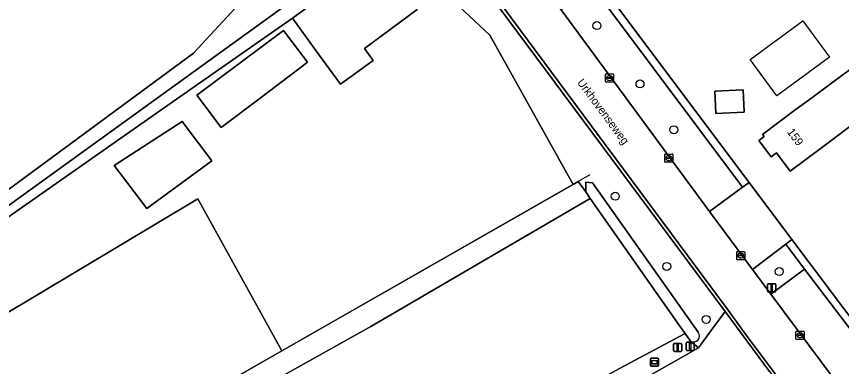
# Model space of a CAD drawing. Extents: x 164494 to 166241, y 382475 to 384495.
# Drawn here: x 164917.8 to 165019, y 383217.5 to 383260.4 of the extents above; entities that cross this region are included whole.
import ezdxf

# ---------------------------------------------------------------- set-up
doc = ezdxf.new("R2010")
doc.units = 0
for name, color, linetype in [('IMGEO_Afsluitpaal', 7, 'Continuous'), ('IMGEO_Berm_halfverhard', 7, 'Continuous'), ('IMGEO_Boom', 7, 'Continuous'), ('IMGEO_Erf', 7, 'Continuous'), ('IMGEO_Grasland_agrarisch', 7, 'Continuous'), ('IMGEO_Grasland_overig', 7, 'Continuous'), ('IMGEO_Groenvoorziening', 7, 'Continuous'), ('IMGEO_Hek', 7, 'Continuous'), ('IMGEO_Informatiebord', 7, 'Continuous'), ('IMGEO_Kolk', 7, 'Continuous'), ('IMGEO_Lichtmast', 7, 'Continuous'), ('IMGEO_Openbare_ruimte_label', 7, 'Continuous'), ('IMGEO_Pand', 7, 'Continuous'), ('IMGEO_Pand_nummerreeks', 7, 'Continuous'), ('IMGEO_Pand_vergunning_verleend', 7, 'Continuous'), ('IMGEO_Parkeervlak_open', 7, 'Continuous'), ('IMGEO_Rijbaan_lokaal_gesloten', 7, 'Continuous'), ('IMGEO_Voetpad_halfverhard', 7, 'Continuous'), ('IMGEO_Voetpad_open', 7, 'Continuous'), ('IMGEO_Waterloop', 7, 'Continuous')]:
    doc.layers.add(name, color=color, linetype=linetype)

msp = doc.modelspace()

# ---------------------------------------------------------------- linework, layer by layer
at = {"layer": 'IMGEO_Afsluitpaal'}
for p, q in [((165000.02, 383220.51), (165000.81, 383220.51)), ((165000.81, 383220.51), (165000.02, 383220.51)), ((164998.39, 383219.47), (164998.39, 383220.27)), ((164998.39, 383220.27), (164998.39, 383219.47)), ((164998.49, 383220.37), (164999.28, 383220.37)), ((164999.28, 383220.37), (164998.49, 383220.37)), ((164999.38, 383220.27), (164999.38, 383219.47)), ((164999.38, 383219.47), (164999.38, 383220.27)), ((164999.92, 383219.61), (164999.92, 383220.41)), ((164999.92, 383220.41), (164999.92, 383219.61)), ((165000.81, 383219.51), (165000.02, 383219.51)), ((165000.02, 383219.51), (165000.81, 383219.51)), ((165000.91, 383220.41), (165000.91, 383219.61)), ((165000.91, 383219.61), (165000.91, 383220.41)), ((164999.28, 383219.37), (164998.49, 383219.37)), ((164998.49, 383219.37), (164999.28, 383219.37))]:
    msp.add_line(p, q, dxfattribs=at)
for points in [[(164998.81, 383220.24), (164998.96, 383220.24), (164998.96, 383219.49), (164998.81, 383219.49), (164998.81, 383220.24)], [(165000.34, 383220.39), (165000.49, 383220.39), (165000.49, 383219.64), (165000.34, 383219.64), (165000.34, 383220.39)]]:
    msp.add_lwpolyline(points, dxfattribs=at)
for centre, start, end in [((165000.02, 383220.41), 90, 180), ((165000.02, 383220.41), 90, 180), ((165000.81, 383220.41), 0, 90), ((165000.81, 383220.41), 360, 90), ((164998.49, 383220.27), 90, 180), ((164998.49, 383220.27), 90, 180), ((164998.49, 383219.47), 180, 270), ((164998.49, 383219.47), 180, 270), ((164999.28, 383220.27), 0, 90), ((164999.28, 383220.27), 360, 90), ((164999.28, 383219.47), 270, 0), ((164999.28, 383219.47), 270, 0), ((165000.02, 383219.61), 180, 270), ((165000.02, 383219.61), 180, 270), ((165000.81, 383219.61), 270, 0), ((165000.81, 383219.61), 270, 0)]:
    msp.add_arc(centre, 0.1, start, end, dxfattribs=at)
at = {"layer": 'IMGEO_Berm_halfverhard'}
msp.add_lwpolyline([(164958.62, 383286.84), (164958.17, 383286.49), (164958.55, 383285.99), (164958.68, 383286.07), (164960.2, 383284.12), (164981.5, 383255.45), (165004.7, 383224.27), (165010.16, 383216.93), (165012.66, 383213.57), (165041.52, 383174.67), (165059.93, 383149.88), (165074.19, 383130.82), (165074.54, 383131.07), (165010.83, 383216.64), (165007.31, 383221.33), (165004.94, 383224.6), (164967.78, 383274.69)], close=True, dxfattribs=at)
at = {"layer": 'IMGEO_Boom'}
for centre in [(164988.99, 383259.29), (164994.27, 383252.14), (164998.41, 383246.53), (164991.24, 383238.38), (164997.55, 383229.79), (165011.34, 383229.17), (165002.38, 383223.31)]:
    msp.add_circle(centre, 0.489, dxfattribs=at)
at = {"layer": 'IMGEO_Erf'}
msp.add_lwpolyline([(165023.92, 383258.65), (165006.08, 383283.99), (165005.99, 383284.12), (164985.66, 383269.16), (164989.23, 383264.62), (164989.47, 383264.32), (165007.64, 383240.09), (165012.9, 383233.07), (165015.24, 383229.95), (165031.24, 383208.7)], dxfattribs=at)
for points in [[(164975.85, 383258.13), (164970.17, 383263.46), (164965.56, 383269.95), (164955.81, 383263.21), (164956.74, 383261.95), (164963.02, 383266.55), (164966.97, 383261.24), (164960.49, 383256.48), (164961.55, 383255.02), (164957.55, 383252.11), (164954.88, 383255.78), (164951.66, 383260.2), (164937.06, 383250), (164897.83, 383222.54), (164900.71, 383215.89), (164901.16, 383214.86), (164940.07, 383238.06), (164950.37, 383219.45), (164986.06, 383239.83)], [(164942.93, 383246.82), (164939.97, 383250.76), (164950.58, 383258.7), (164953.52, 383254.79), (164952.62, 383254.12), (164947.54, 383250.29)], [(165016.69, 383244.44), (165012.69, 383241.44), (165010.98, 383243.72), (165010.33, 383243.23), (165008.84, 383245.21), (165009.49, 383245.7), (165009.3, 383245.95), (165013.3, 383248.95), (165014.72, 383250), (165019.93, 383253.86), (165021.79, 383251.27), (165023.19, 383249.33), (165021.63, 383248.16)], [(165003.56, 383248.53), (165003.45, 383251.26), (165006.92, 383251.41), (165007.04, 383248.68)], [(164941.79, 383242.72), (164933.81, 383236.88), (164929.82, 383242.15), (164938.15, 383247.53)]]:
    msp.add_lwpolyline(points, close=True, dxfattribs=at)
at = {"layer": 'IMGEO_Grasland_agrarisch'}
for points in [[(164934.11, 383311.92), (164929.02, 383318.47), (164901.77, 383355.27), (164897.46, 383360.39), (164834.21, 383297.03), (164834.1, 383296.91), (164881.99, 383247.23), (164898.48, 383225.71), (164939.55, 383255.93), (164960.04, 383278.08), (164955.63, 383284.19), (164935.17, 383310.55), (164875.47, 383265.01), (164875, 383265.61)], [(164903.86, 383190.4), (164907.46, 383171.6), (164949.35, 383194.41), (164992.36, 383217.63), (164999.81, 383221.56), (164999.17, 383222.48), (164988.18, 383238.12), (164961.27, 383222.45)]]:
    msp.add_lwpolyline(points, close=True, dxfattribs=at)
at = {"layer": 'IMGEO_Grasland_overig'}
for points in [[(164959.97, 383268.39), (164897.51, 383223.29), (164897.83, 383222.54), (164937.06, 383250), (164951.66, 383260.2), (164955.81, 383263.21), (164965.56, 383269.95), (164963.61, 383272.68)], [(164961.27, 383222.45), (164988.18, 383238.12), (164987.61, 383238.93), (164986.71, 383240.2), (164986.06, 383239.83), (164950.37, 383219.45), (164903.43, 383192.65), (164903.86, 383190.4)], [(164901.16, 383214.86), (164899.35, 383213.93), (164903.43, 383192.65), (164950.37, 383219.45), (164940.07, 383238.06)]]:
    msp.add_lwpolyline(points, close=True, dxfattribs=at)
at = {"layer": 'IMGEO_Groenvoorziening'}
for points in [[(164947.02, 383302.56), (164946.53, 383302.21), (164898.89, 383366.18), (164896.81, 383364), (164902.87, 383356.58), (164911.4, 383344.92), (164923.31, 383329.12), (164956.87, 383285.13), (164961.24, 383279.38), (164965.05, 383274.38), (164963.61, 383272.68), (164965.56, 383269.95), (164970.17, 383263.46), (164975.85, 383258.13), (164986.06, 383239.83), (164986.71, 383240.2), (164987.61, 383238.93), (164987.64, 383240.13), (164988.45, 383240.02), (165001.41, 383221.73)], [(165000.46, 383220.63), (165001.45, 383219.83), (165002.52, 383221.3), (165004.7, 383224.27), (164981.5, 383255.45), (164960.2, 383284.12), (164958.68, 383286.07), (164958.55, 383285.99), (164958.17, 383286.49), (164958.62, 383286.84), (164957.5, 383288.33), (164947.9, 383301.37), (164947.02, 383302.56)], [(164893.14, 383182.75), (164895.68, 383166.32), (164897.42, 383160.93), (164911.35, 383169.35), (164968.99, 383201.4), (165001.45, 383219.83), (165000.46, 383220.63), (164999.81, 383221.56), (164992.36, 383217.63), (164949.35, 383194.41), (164907.46, 383171.6), (164906.33, 383170.97)]]:
    msp.add_lwpolyline(points, dxfattribs=at)
for points in [[(164959.97, 383268.39), (164963.61, 383272.68), (164965.05, 383274.38), (164961.24, 383279.38), (164960.04, 383278.08), (164939.55, 383255.93), (164898.48, 383225.71), (164881.99, 383247.23), (164834.1, 383296.91), (164832.08, 383294.55), (164858.39, 383267.87), (164865.29, 383260.63), (164875.01, 383250), (164882.15, 383241.83), (164888.04, 383234.54), (164892.14, 383229.16), (164896.71, 383222.7), (164897.51, 383223.29)], [(164984.61, 383261.22), (165002.79, 383236.5), (165006.84, 383239.5), (164990.66, 383261.09), (164988.36, 383263.98)], [(165008.04, 383229.43), (165010.32, 383226.4), (165014.43, 383229.45), (165012.16, 383232.51)]]:
    msp.add_lwpolyline(points, close=True, dxfattribs=at)
msp.add_arc((165000.83, 383221.27), 0.737, 240.1608, 37.9146, dxfattribs=at)
at = {"layer": 'IMGEO_Hek'}
for points in [[(164988.13, 383241.01), (164986.71, 383240.2)], [(164986.71, 383240.2), (164950.37, 383219.45), (164903.43, 383192.65)]]:
    msp.add_lwpolyline(points, dxfattribs=at)
at = {"layer": 'IMGEO_Informatiebord'}
for p, q in [((164995.55, 383217.66), (164995.55, 383218.46)), ((164995.55, 383218.46), (164995.55, 383217.66)), ((164995.65, 383218.56), (164996.44, 383218.56)), ((164996.44, 383218.56), (164995.65, 383218.56)), ((164996.54, 383218.46), (164996.54, 383217.66)), ((164996.54, 383217.66), (164996.54, 383218.46)), ((164996.44, 383217.56), (164995.65, 383217.56)), ((164995.65, 383217.56), (164996.44, 383217.56))]:
    msp.add_line(p, q, dxfattribs=at)
for points in [[(164995.65, 383218.29), (164996.44, 383218.29), (164996.44, 383217.82), (164995.65, 383217.82), (164995.65, 383218.29)], [(164995.72, 383218.22), (164995.72, 383217.89), (164996.37, 383217.89), (164996.37, 383218.22), (164995.72, 383218.22)]]:
    msp.add_lwpolyline(points, dxfattribs=at)
for centre, start, end in [((164995.65, 383218.46), 90, 180), ((164995.65, 383218.46), 90, 180), ((164996.44, 383218.46), 0, 90), ((164996.44, 383218.46), 360, 90), ((164995.65, 383217.66), 180, 270), ((164995.65, 383217.66), 180, 270), ((164996.44, 383217.66), 270, 0), ((164996.44, 383217.66), 270, 0)]:
    msp.add_arc(centre, 0.1, start, end, dxfattribs=at)
at = {"layer": 'IMGEO_Kolk'}
for p, q in [((164990.04, 383252.44), (164990.04, 383253.29)), ((164990.11, 383253.36), (164990.97, 383253.36)), ((164990.3, 383252.86), (164990.3, 383252.87)), ((164990.34, 383252.91), (164990.74, 383252.91)), ((164990.73, 383252.82), (164990.34, 383252.82)), ((164990.53, 383253.14), (164990.55, 383253.14)), ((164990.78, 383252.87), (164990.78, 383252.86)), ((164991.04, 383253.29), (164991.04, 383252.44)), ((164990.97, 383252.36), (164990.11, 383252.36)), ((164990.55, 383252.58), (164990.52, 383252.58)), ((164997.3, 383242.63), (164997.3, 383243.48)), ((164997.37, 383243.55), (164998.22, 383243.55)), ((164997.56, 383243.05), (164997.56, 383243.06)), ((164997.6, 383243.1), (164998, 383243.1)), ((164997.99, 383243.01), (164997.6, 383243.01)), ((164997.81, 383242.77), (164997.78, 383242.77)), ((164997.79, 383243.33), (164997.81, 383243.33)), ((164998.04, 383243.06), (164998.04, 383243.05)), ((164998.3, 383243.48), (164998.3, 383242.63)), ((164998.22, 383242.55), (164997.37, 383242.55)), ((165006.12, 383230.69), (165006.12, 383231.55)), ((165006.19, 383231.62), (165007.04, 383231.62)), ((165007.12, 383231.55), (165007.12, 383230.69)), ((165007.04, 383230.62), (165006.19, 383230.62)), ((165006.37, 383231.11), (165006.37, 383231.13)), ((165006.81, 383231.08), (165006.41, 383231.08)), ((165006.42, 383231.16), (165006.81, 383231.16)), ((165006.6, 383231.4), (165006.63, 383231.4)), ((165006.63, 383230.84), (165006.6, 383230.84)), ((165006.86, 383231.13), (165006.86, 383231.11)), ((165013.38, 383220.93), (165013.38, 383221.79)), ((165013.46, 383221.86), (165014.31, 383221.86)), ((165013.87, 383221.64), (165013.9, 383221.64)), ((165014.39, 383221.79), (165014.39, 383220.93)), ((165014.31, 383220.86), (165013.46, 383220.86)), ((165013.64, 383221.35), (165013.64, 383221.37)), ((165014.08, 383221.32), (165013.68, 383221.32)), ((165013.69, 383221.4), (165014.08, 383221.4)), ((165013.89, 383221.08), (165013.87, 383221.08)), ((165014.13, 383221.37), (165014.13, 383221.35))]:
    msp.add_line(p, q, dxfattribs=at)
for points in [[(164990.04, 383252.44), (164990.04, 383253.29)], [(164990.11, 383253.36), (164990.97, 383253.36)], [(164991.04, 383253.29), (164991.04, 383252.44)], [(164990.97, 383252.36), (164990.11, 383252.36)], [(164997.3, 383242.63), (164997.3, 383243.48)], [(164997.37, 383243.55), (164998.22, 383243.55)], [(164998.3, 383243.48), (164998.3, 383242.63)], [(164998.22, 383242.55), (164997.37, 383242.55)], [(165006.12, 383230.69), (165006.12, 383231.55)], [(165006.19, 383231.62), (165007.04, 383231.62)], [(165007.12, 383231.55), (165007.12, 383230.69)], [(165007.04, 383230.62), (165006.19, 383230.62)], [(165013.38, 383220.93), (165013.38, 383221.79)], [(165013.46, 383221.86), (165014.31, 383221.86)], [(165014.39, 383221.79), (165014.39, 383220.93)], [(165014.31, 383220.86), (165013.46, 383220.86)]]:
    msp.add_lwpolyline(points, dxfattribs=at)
for centre, radius, start, end in [((164990.11, 383253.29), 0.0765, 91.552, 178.448), ((164990.11, 383253.29), 0.0765, 91.552, 178.448), ((164990.34, 383252.87), 0.0403, 85.8775, 175.7526), ((164990.33, 383252.86), 0.0366, 178.938, 274.7102), ((164990.74, 383252.86), 0.043, 264.8664, 352.4533), ((164990.74, 383252.87), 0.0386, 1.7309, 96.639), ((164990.96, 383253.29), 0.0765, 1.552, 88.448), ((164990.96, 383253.29), 0.0765, 1.552, 88.448), ((164990.11, 383252.44), 0.0765, 181.552, 268.448), ((164990.11, 383252.44), 0.0765, 181.552, 268.448), ((164990.96, 383252.44), 0.0765, 271.552, 358.448), ((164990.96, 383252.44), 0.0765, 271.552, 358.448), ((164997.37, 383243.48), 0.0765, 91.552, 178.448), ((164997.37, 383243.48), 0.0765, 91.552, 178.448), ((164997.6, 383243.06), 0.0403, 85.8775, 175.7526), ((164997.59, 383243.05), 0.0366, 178.938, 274.7102), ((164998, 383243.05), 0.043, 264.8664, 352.4533), ((164998, 383243.06), 0.0386, 1.7309, 96.639), ((164998.22, 383243.48), 0.0765, 1.552, 88.448), ((164998.22, 383243.48), 0.0765, 1.552, 88.448), ((164997.37, 383242.63), 0.0765, 181.552, 268.448), ((164997.37, 383242.63), 0.0765, 181.552, 268.448), ((164998.22, 383242.63), 0.0765, 271.552, 358.448), ((164998.22, 383242.63), 0.0765, 271.552, 358.448), ((165006.19, 383231.54), 0.0765, 91.552, 178.448), ((165006.19, 383231.54), 0.0765, 91.552, 178.448), ((165007.04, 383231.54), 0.0765, 1.552, 88.448), ((165007.04, 383231.54), 0.0765, 1.552, 88.448), ((165006.19, 383230.7), 0.0765, 181.552, 268.448), ((165006.19, 383230.7), 0.0765, 181.552, 268.448), ((165006.41, 383231.12), 0.0403, 85.8775, 175.7526), ((165006.41, 383231.11), 0.0366, 178.938, 274.7102), ((165006.82, 383231.12), 0.0386, 1.7309, 96.639), ((165006.82, 383231.12), 0.043, 264.8664, 352.4533), ((165007.04, 383230.7), 0.0765, 271.552, 358.448), ((165007.04, 383230.7), 0.0765, 271.552, 358.448), ((165013.46, 383221.78), 0.0765, 91.552, 178.448), ((165013.46, 383221.78), 0.0765, 91.552, 178.448), ((165014.31, 383221.78), 0.0765, 1.552, 88.448), ((165014.31, 383221.78), 0.0765, 1.552, 88.448), ((165013.46, 383220.93), 0.0765, 181.552, 268.448), ((165013.46, 383220.93), 0.0765, 181.552, 268.448), ((165013.68, 383221.36), 0.0403, 85.8775, 175.7526), ((165013.68, 383221.35), 0.0366, 178.938, 274.7102), ((165014.09, 383221.36), 0.0386, 1.7309, 96.639), ((165014.08, 383221.36), 0.043, 264.8664, 352.4533), ((165014.31, 383220.93), 0.0765, 271.552, 358.448), ((165014.31, 383220.93), 0.0765, 271.552, 358.448)]:
    msp.add_arc(centre, radius, start, end, dxfattribs=at)
for centre, major_axis, ratio, start_param, end_param in [((164990.53, 383252.86), (-0.387, 0.002), 0.722429, 4.712389, 7.853982), ((164990.55, 383252.86), (-0.39, 0.002), 0.717154, 1.570796, 4.712389), ((164997.78, 383243.05), (-0.387, 0.002), 0.722429, 4.712389, 7.853982), ((164997.81, 383243.05), (-0.39, 0.002), 0.717154, 1.570796, 4.712389), ((165006.6, 383231.12), (-0.387, 0.002), 0.722429, 4.712389, 7.853982), ((165006.63, 383231.12), (-0.39, 0.002), 0.717154, 1.570796, 4.712389), ((165013.87, 383221.36), (-0.387, 0.002), 0.722429, 4.712389, 7.853982), ((165013.9, 383221.36), (-0.39, 0.002), 0.717154, 1.570796, 4.712389)]:
    msp.add_ellipse(centre, major_axis=major_axis, ratio=ratio, start_param=start_param, end_param=end_param, dxfattribs=at)
at = {"layer": 'IMGEO_Lichtmast'}
for p, q in [((165009.91, 383226.77), (165009.91, 383227.57)), ((165009.91, 383227.57), (165009.91, 383226.77)), ((165010.01, 383227.67), (165010.8, 383227.67)), ((165010.8, 383227.67), (165010.01, 383227.67)), ((165010.9, 383227.57), (165010.9, 383226.77)), ((165010.9, 383226.77), (165010.9, 383227.57)), ((165010.8, 383226.67), (165010.01, 383226.67)), ((165010.01, 383226.67), (165010.8, 383226.67))]:
    msp.add_line(p, q, dxfattribs=at)
msp.add_lwpolyline([(165010.33, 383227.54), (165010.48, 383227.54), (165010.48, 383226.79), (165010.33, 383226.79), (165010.33, 383227.54)], dxfattribs=at)
for centre, start, end in [((165010.01, 383227.57), 90, 180), ((165010.01, 383227.57), 90, 180), ((165010.8, 383227.57), 0, 90), ((165010.8, 383227.57), 360, 90), ((165010.01, 383226.77), 180, 270), ((165010.01, 383226.77), 180, 270), ((165010.8, 383226.77), 270, 0), ((165010.8, 383226.77), 270, 0)]:
    msp.add_arc(centre, 0.1, start, end, dxfattribs=at)
at = {"layer": 'IMGEO_Pand'}
for points in [[(164951.66, 383260.2), (164954.88, 383255.78), (164957.55, 383252.11), (164961.55, 383255.02), (164960.49, 383256.48), (164966.97, 383261.24), (164963.02, 383266.55), (164956.74, 383261.95), (164955.81, 383263.21)], [(164939.97, 383250.76), (164942.93, 383246.82), (164947.54, 383250.29), (164952.62, 383254.12), (164953.52, 383254.79), (164950.58, 383258.7)], [(165021.63, 383248.16), (165023.19, 383249.33), (165021.79, 383251.27), (165019.93, 383253.86), (165014.72, 383250), (165013.3, 383248.95), (165009.3, 383245.95), (165009.49, 383245.7), (165008.84, 383245.21), (165010.33, 383243.23), (165010.98, 383243.72), (165012.69, 383241.44), (165016.69, 383244.44)], [(165006.92, 383251.41), (165003.45, 383251.26), (165003.56, 383248.53), (165007.04, 383248.68)], [(164941.79, 383242.72), (164938.15, 383247.53), (164929.82, 383242.15), (164933.81, 383236.88)]]:
    msp.add_lwpolyline(points, close=True, dxfattribs=at)
at = {"layer": 'IMGEO_Pand_vergunning_verleend'}
msp.add_lwpolyline([(165014.24, 383259.86), (165017.49, 383255.42), (165011.05, 383250.69), (165007.79, 383255.12)], close=True, dxfattribs=at)
at = {"layer": 'IMGEO_Parkeervlak_open'}
for points in [[(165002.79, 383236.5), (165008.04, 383229.43), (165012.16, 383232.51), (165012.9, 383233.07), (165007.64, 383240.09), (165006.84, 383239.5)], [(165010.32, 383226.4), (165024.15, 383207.81), (165028.36, 383210.94), (165021.89, 383219.67), (165014.43, 383229.45)]]:
    msp.add_lwpolyline(points, close=True, dxfattribs=at)
at = {"layer": 'IMGEO_Rijbaan_lokaal_gesloten'}
msp.add_lwpolyline([(165024.15, 383207.81), (165010.32, 383226.4), (165008.04, 383229.43), (165002.79, 383236.5), (164984.61, 383261.22), (164980.6, 383266.49), (164979.77, 383267.57), (164979.46, 383267.35), (164963.99, 383288.23), (164961.64, 383291.4), (164957.5, 383288.33), (164958.62, 383286.84), (164967.78, 383274.69), (165004.94, 383224.6), (165007.31, 383221.33), (165010.83, 383216.64), (165074.54, 383131.07)], dxfattribs=at)
at = {"layer": 'IMGEO_Voetpad_halfverhard'}
msp.add_lwpolyline([(165010.16, 383216.93), (165004.7, 383224.27), (165002.52, 383221.3), (165001.45, 383219.83), (164968.99, 383201.4), (164911.35, 383169.35), (164897.42, 383160.93), (164899.57, 383159.05), (164902.57, 383160.66), (164912.88, 383166.29)], dxfattribs=at)
at = {"layer": 'IMGEO_Voetpad_open'}
for points in [[(165007.64, 383240.09), (164989.47, 383264.32), (164989.23, 383264.62), (164988.36, 383263.98), (164990.66, 383261.09), (165006.84, 383239.5)], [(165012.16, 383232.51), (165014.43, 383229.45), (165021.89, 383219.67), (165028.36, 383210.94), (165030.49, 383208.13), (165031.24, 383208.7), (165015.24, 383229.95), (165012.9, 383233.07)]]:
    msp.add_lwpolyline(points, close=True, dxfattribs=at)
at = {"layer": 'IMGEO_Waterloop'}
for points in [[(165001.41, 383221.73), (164988.45, 383240.02), (164987.64, 383240.13), (164987.61, 383238.93)], [(164987.61, 383238.93), (164988.18, 383238.12), (164999.17, 383222.48), (164999.81, 383221.56), (165000.46, 383220.63)]]:
    msp.add_lwpolyline(points, dxfattribs=at)
msp.add_arc((165000.83, 383221.27), 0.737, 240.1608, 37.9146, dxfattribs=at)

# ---------------------------------------------------------------- texts
at = {"layer": 'IMGEO_Openbare_ruimte_label'}
msp.add_text('Urkhovenseweg', height=1, rotation=306.5834, dxfattribs=at).set_placement((164986.51, 383252.31))
at = {"layer": 'IMGEO_Pand_nummerreeks'}
msp.add_text('159', height=1, rotation=306.9269, dxfattribs=at).set_placement((165012.24, 383246.24))

doc.saveas('drawing.dxf')
